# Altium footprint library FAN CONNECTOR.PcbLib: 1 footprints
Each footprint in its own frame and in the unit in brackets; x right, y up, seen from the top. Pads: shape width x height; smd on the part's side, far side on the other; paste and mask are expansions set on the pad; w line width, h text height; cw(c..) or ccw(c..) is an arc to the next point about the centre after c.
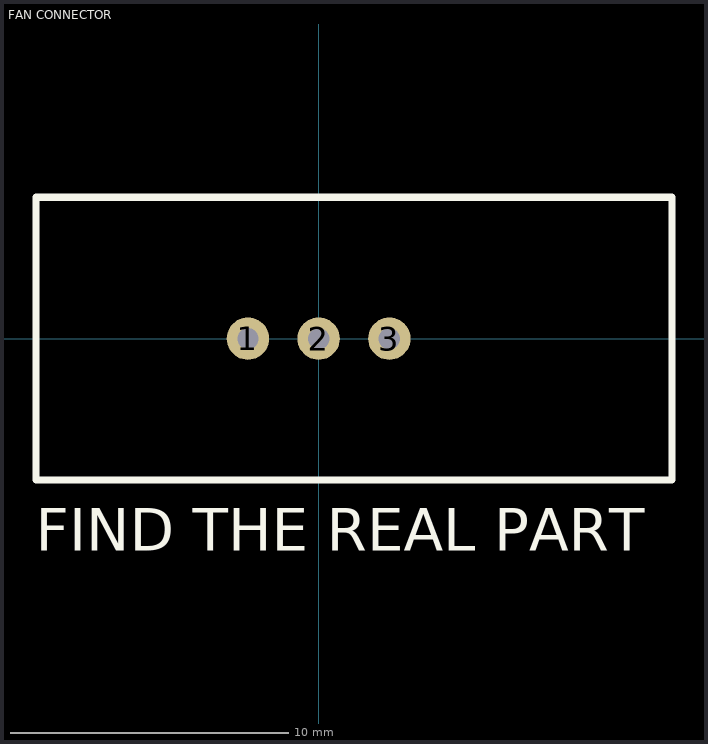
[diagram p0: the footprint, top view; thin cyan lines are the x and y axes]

## FAN CONNECTOR [mil]
height 393.7
pads (3):
  round 60 hole 30: 1(-100,0) 2(0,0) 3(100,0)
Top Overlay:
  lines w10: -400,-200 500,-200 500,200 -400,200 -400,-200
  text "FIND THE REAL PART" at -400,-300 h60
M5 Assembly Top:
  text ".Designator" at -60,-20 h40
